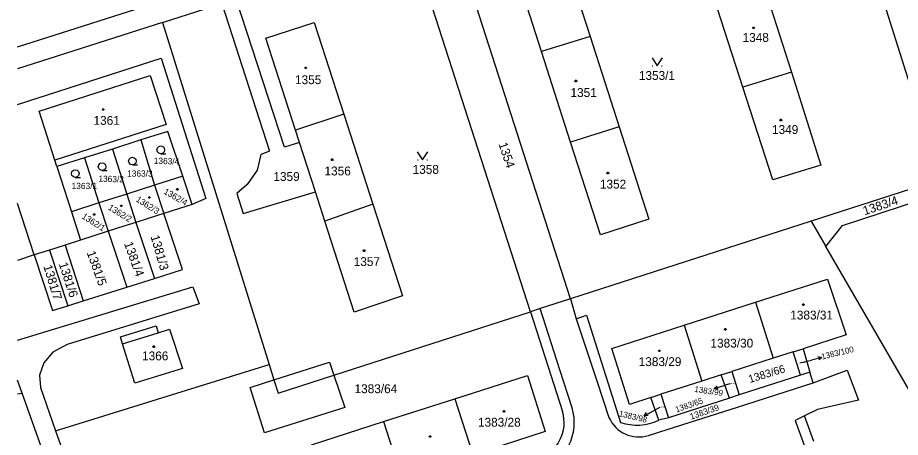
# Model space of a CAD drawing. Extents: x -621797 to -620972, y -1175539 to -1174697.
# Drawn here: x -621790.3 to -621620.7, y -1175421.5 to -1175341 of the extents above; entities that cross this region are included whole.
import ezdxf

# ---------------------------------------------------------------- set-up
doc = ezdxf.new("R2010")
doc.units = 0
for name, color, linetype in [('INZ mimo EON - nadz', 7, 'Continuous'), ('Rozvod plynu EON', 7, 'Continuous'), ('SDEL EON', 7, 'Continuous'), ('SDEL EON - popis', 7, 'Continuous'), ('Silnoproud EON', 7, 'Continuous'), ('Silnoproud EON - popis', 7, 'Continuous')]:
    doc.layers.add(name, color=color, linetype=linetype)

msp = doc.modelspace()

# ---------------------------------------------------------------- linework, layer by layer
at = {"layer": 'INZ mimo EON - nadz'}
for p, q in [((-621639.98, -1175407.25), (-621637.75, -1175406.68)), ((-621635.807, -1175406.166), (-621637.75, -1175406.68)), ((-621656.444, -1175412.173), (-621654.52, -1175411.59)), ((-621653.46, -1175411.26), (-621654.52, -1175411.59)), ((-621669.899, -1175417.383), (-621668.13, -1175416.43)), ((-621666.93, -1175415.8), (-621668.13, -1175416.43))]:
    msp.add_line(p, q, dxfattribs=at)
for points in [[(-621636.54, -1175406.013), (-621635.807, -1175406.166), (-621636.369, -1175406.661)], [(-621655.705, -1175412.299), (-621656.444, -1175412.173), (-621655.9, -1175411.658)], [(-621669.151, -1175417.361), (-621669.899, -1175417.383), (-621669.469, -1175416.771)]]:
    msp.add_lwpolyline(points, dxfattribs=at)
at = {"layer": 'Rozvod plynu EON'}
for points in [[(-621648.8, -1175342.77), (-621648.71, -1175342.92), (-621648.8, -1175343.07), (-621648.98, -1175343.07), (-621649.07, -1175342.92), (-621648.98, -1175342.77)], [(-621734.88, -1175350.45), (-621734.79, -1175350.6), (-621734.88, -1175350.75), (-621735.06, -1175350.75), (-621735.15, -1175350.6), (-621735.06, -1175350.45)], [(-621682.94, -1175352.95), (-621682.85, -1175353.1), (-621682.94, -1175353.25), (-621683.12, -1175353.25), (-621683.21, -1175353.1), (-621683.12, -1175352.95)], [(-621773.79, -1175358.44), (-621773.7, -1175358.59), (-621773.79, -1175358.74), (-621773.97, -1175358.74), (-621774.06, -1175358.59), (-621773.97, -1175358.44)], [(-621643.56, -1175360.44), (-621643.47, -1175360.59), (-621643.56, -1175360.74), (-621643.74, -1175360.74), (-621643.83, -1175360.59), (-621643.74, -1175360.44)], [(-621729.78, -1175368.05), (-621729.69, -1175368.2), (-621729.78, -1175368.35), (-621729.96, -1175368.35), (-621730.05, -1175368.2), (-621729.96, -1175368.05)], [(-621676.8, -1175370.62), (-621676.71, -1175370.77), (-621676.8, -1175370.92), (-621676.98, -1175370.92), (-621677.07, -1175370.77), (-621676.98, -1175370.62)], [(-621759.54, -1175373.78), (-621759.45, -1175373.93), (-621759.54, -1175374.08), (-621759.72, -1175374.08), (-621759.81, -1175373.93), (-621759.72, -1175373.78)], [(-621764.92, -1175375.33), (-621764.83, -1175375.48), (-621764.92, -1175375.63), (-621765.1, -1175375.63), (-621765.19, -1175375.48), (-621765.1, -1175375.33)], [(-621770.3, -1175376.94), (-621770.21, -1175377.09), (-621770.3, -1175377.24), (-621770.48, -1175377.24), (-621770.57, -1175377.09), (-621770.48, -1175376.94)], [(-621775.51, -1175378.6), (-621775.42, -1175378.75), (-621775.51, -1175378.9), (-621775.69, -1175378.9), (-621775.78, -1175378.75), (-621775.69, -1175378.6)], [(-621723.65, -1175385.54), (-621723.56, -1175385.69), (-621723.65, -1175385.84), (-621723.83, -1175385.84), (-621723.92, -1175385.69), (-621723.83, -1175385.54)], [(-621639.25, -1175395.92), (-621639.16, -1175396.07), (-621639.25, -1175396.22), (-621639.43, -1175396.22), (-621639.52, -1175396.07), (-621639.43, -1175395.92)], [(-621654.23, -1175400.65), (-621654.14, -1175400.8), (-621654.23, -1175400.95), (-621654.41, -1175400.95), (-621654.5, -1175400.8), (-621654.41, -1175400.65)], [(-621764.06, -1175403.95), (-621763.97, -1175404.1), (-621764.06, -1175404.25), (-621764.24, -1175404.25), (-621764.33, -1175404.1), (-621764.24, -1175403.95)], [(-621666.92, -1175404.77), (-621666.83, -1175404.92), (-621666.92, -1175405.07), (-621667.1, -1175405.07), (-621667.19, -1175404.92), (-621667.1, -1175404.77)], [(-621696.76, -1175416.36), (-621696.67, -1175416.51), (-621696.76, -1175416.66), (-621696.94, -1175416.66), (-621697.03, -1175416.51), (-621696.94, -1175416.36)], [(-621710.97, -1175421.21), (-621710.88, -1175421.36), (-621710.97, -1175421.51), (-621711.15, -1175421.51), (-621711.24, -1175421.36), (-621711.15, -1175421.21)]]:
    msp.add_lwpolyline(points, close=True, dxfattribs=at)
at = {"layer": 'SDEL EON'}
for p, q in [((-621668.36, -1175350.19), (-621668.26, -1175350.19)), ((-621666.56, -1175350.19), (-621666.46, -1175350.19)), ((-621713.46, -1175368.24), (-621713.36, -1175368.24)), ((-621711.66, -1175368.24), (-621711.56, -1175368.24))]:
    msp.add_line(p, q, dxfattribs=at)
for points in [[(-621668.41, -1175348.69), (-621667.41, -1175350.19), (-621666.41, -1175348.69)], [(-621762.79, -1175367.07), (-621763.17, -1175366.97), (-621763.44, -1175366.7), (-621763.54, -1175366.33), (-621763.44, -1175365.96), (-621763.17, -1175365.69), (-621762.8, -1175365.59), (-621762.43, -1175365.69), (-621762.16, -1175365.96), (-621762.06, -1175366.34), (-621762.16, -1175366.72), (-621762.43, -1175366.99), (-621762.81, -1175367.09), (-621761.81, -1175367.09)], [(-621768.25, -1175369.22), (-621768.63, -1175369.12), (-621768.9, -1175368.85), (-621769, -1175368.48), (-621768.9, -1175368.11), (-621768.63, -1175367.84), (-621768.26, -1175367.74), (-621767.89, -1175367.84), (-621767.62, -1175368.11), (-621767.52, -1175368.49), (-621767.62, -1175368.87), (-621767.89, -1175369.14), (-621768.27, -1175369.24), (-621767.27, -1175369.24)], [(-621713.51, -1175366.74), (-621712.51, -1175368.24), (-621711.51, -1175366.74)], [(-621774.09, -1175370.3), (-621774.47, -1175370.2), (-621774.74, -1175369.93), (-621774.84, -1175369.56), (-621774.74, -1175369.19), (-621774.47, -1175368.92), (-621774.1, -1175368.82), (-621773.73, -1175368.92), (-621773.46, -1175369.19), (-621773.36, -1175369.57), (-621773.46, -1175369.95), (-621773.73, -1175370.22), (-621774.11, -1175370.32), (-621773.11, -1175370.32)], [(-621779.22, -1175371.62), (-621779.6, -1175371.52), (-621779.87, -1175371.25), (-621779.97, -1175370.88), (-621779.87, -1175370.51), (-621779.6, -1175370.24), (-621779.23, -1175370.14), (-621778.86, -1175370.24), (-621778.59, -1175370.51), (-621778.49, -1175370.89), (-621778.59, -1175371.27), (-621778.86, -1175371.54), (-621779.24, -1175371.64), (-621778.24, -1175371.64)]]:
    msp.add_lwpolyline(points, dxfattribs=at)
at = {"layer": 'SDEL EON - popis'}
for p, q in [((-621790.31, -1175346.561), (-621755.77, -1175335.52)), ((-621786.19, -1175358.92), (-621764.84, -1175352.09)), ((-621764.84, -1175352.09), (-621761.79, -1175361.48)), ((-621783.14, -1175368.33), (-621786.19, -1175358.92)), ((-621761.79, -1175361.48), (-621783.14, -1175368.33)), ((-621782.75, -1175369.56), (-621783.14, -1175368.33)), ((-621770.15, -1175403.57), (-621763.29, -1175401.44)), ((-621741.05, -1175410.49), (-621730.39, -1175407.07)), ((-621730.39, -1175407.07), (-621729.54, -1175409.59)), ((-621745.62, -1175411.95), (-621741.05, -1175410.49)), ((-621729.54, -1175409.59), (-621727.46, -1175415.77)), ((-621742.86, -1175420.65), (-621745.62, -1175411.95)), ((-621727.46, -1175415.77), (-621742.86, -1175420.65))]:
    msp.add_line(p, q, dxfattribs=at)
at = {"layer": 'Silnoproud EON'}
for p, q in [((-621684.09, -1175394.94), (-621706.99, -1175323.82)), ((-621691.78, -1175397.42), (-621714.66, -1175326.34)), ((-621686.01, -1175326.76), (-621680.29, -1175344.56)), ((-621689.64, -1175347.47), (-621695.36, -1175329.7)), ((-621647.19, -1175333.9), (-621641.63, -1175351.45)), ((-621617.7, -1175357.4), (-621624.53, -1175335.83)), ((-621739.01, -1175365.79), (-621748.33, -1175337.34)), ((-621650.96, -1175354.32), (-621656.61, -1175336.8)), ((-621762.48, -1175341.91), (-621751.05, -1175338.26)), ((-621751.05, -1175338.26), (-621741.9, -1175366.61)), ((-621762.48, -1175341.91), (-621790.31, -1175350.792)), ((-621762.48, -1175341.91), (-621741.97, -1175407.54)), ((-621742.62, -1175344.91), (-621733.31, -1175341.91)), ((-621733.31, -1175341.91), (-621727.62, -1175359.51)), ((-621736.92, -1175362.55), (-621742.62, -1175344.91)), ((-621680.29, -1175344.56), (-621689.64, -1175347.47)), ((-621680.29, -1175344.56), (-621674.72, -1175361.89)), ((-621684.05, -1175364.85), (-621689.64, -1175347.47)), ((-621790.31, -1175357.631), (-621762.76, -1175348.73)), ((-621762.76, -1175348.73), (-621754.14, -1175375.67)), ((-621641.63, -1175351.45), (-621650.96, -1175354.32)), ((-621641.63, -1175351.45), (-621635.98, -1175369.27)), ((-621645.22, -1175372.11), (-621650.96, -1175354.32)), ((-621727.62, -1175359.51), (-621736.92, -1175362.55)), ((-621727.62, -1175359.51), (-621722.04, -1175376.78)), ((-621761.43, -1175362.8), (-621766.62, -1175364.44)), ((-621758.58, -1175371.37), (-621761.43, -1175362.8)), ((-621736.15, -1175364.91), (-621736.92, -1175362.55)), ((-621674.72, -1175361.89), (-621684.05, -1175364.85)), ((-621674.72, -1175361.89), (-621669.01, -1175379.63)), ((-621766.62, -1175364.44), (-621772.08, -1175366.18)), ((-621766.62, -1175364.44), (-621764.01, -1175373.1)), ((-621772.08, -1175366.18), (-621777.46, -1175367.88)), ((-621772.08, -1175366.18), (-621769.34, -1175374.81)), ((-621736.15, -1175364.91), (-621739.01, -1175365.79)), ((-621733.08, -1175374.42), (-621736.15, -1175364.91)), ((-621678.32, -1175382.66), (-621684.05, -1175364.85)), ((-621777.46, -1175367.88), (-621782.75, -1175369.56)), ((-621777.46, -1175367.88), (-621774.71, -1175376.52)), ((-621743.58, -1175367.24), (-621744.3, -1175370.23)), ((-621741.9, -1175366.61), (-621743.58, -1175367.24)), ((-621782.75, -1175369.56), (-621779.99, -1175378.21)), ((-621635.98, -1175369.27), (-621645.22, -1175372.11)), ((-621758.58, -1175371.37), (-621764.01, -1175373.1)), ((-621756.77, -1175376.83), (-621758.58, -1175371.37)), ((-621744.3, -1175370.23), (-621746.19, -1175373)), ((-621764.01, -1175373.1), (-621769.34, -1175374.81)), ((-621764.01, -1175373.1), (-621762.24, -1175378.57)), ((-621746.19, -1175373), (-621748.21, -1175374.71)), ((-621615.01, -1175372.67), (-621637.81, -1175380.02)), ((-621769.34, -1175374.81), (-621774.71, -1175376.52)), ((-621769.34, -1175374.81), (-621767.57, -1175380.27)), ((-621748.21, -1175374.71), (-621746.95, -1175378.56)), ((-621746.95, -1175378.56), (-621733.08, -1175374.42)), ((-621731.27, -1175380.03), (-621733.08, -1175374.42)), ((-621787.11, -1175386.5), (-621790.31, -1175376.66)), ((-621774.71, -1175376.52), (-621779.99, -1175378.21)), ((-621774.71, -1175376.52), (-621772.91, -1175381.97)), ((-621754.14, -1175375.67), (-621756.77, -1175376.83)), ((-621631.78, -1175380.83), (-621614.31, -1175375.13)), ((-621779.99, -1175378.21), (-621778.25, -1175383.67)), ((-621759.22, -1175377.61), (-621762.24, -1175378.57)), ((-621756.77, -1175376.83), (-621759.22, -1175377.61)), ((-621722.04, -1175376.78), (-621731.27, -1175380.03)), ((-621722.04, -1175376.78), (-621716.36, -1175394.34)), ((-621765.21, -1175379.52), (-621767.57, -1175380.27)), ((-621762.24, -1175378.57), (-621765.21, -1175379.52)), ((-621758.64, -1175389.32), (-621762.24, -1175378.57)), ((-621725.63, -1175397.48), (-621731.27, -1175380.03)), ((-621637.81, -1175380.02), (-621684.09, -1175394.94)), ((-621669.01, -1175379.63), (-621678.32, -1175382.66)), ((-621637.81, -1175380.02), (-621634.99, -1175384.89)), ((-621769.91, -1175381.01), (-621772.91, -1175381.97)), ((-621767.57, -1175380.27), (-621769.91, -1175381.01)), ((-621767.57, -1175380.27), (-621764, -1175391.01)), ((-621634.99, -1175384.89), (-621631.78, -1175380.83)), ((-621772.91, -1175381.97), (-621778.25, -1175383.67)), ((-621772.91, -1175381.97), (-621769.36, -1175392.7)), ((-621781.2, -1175384.61), (-621784.16, -1175385.56)), ((-621778.25, -1175383.67), (-621781.2, -1175384.61)), ((-621781.2, -1175384.61), (-621777.69, -1175395.32)), ((-621618.63, -1175413.08), (-621634.99, -1175384.89)), ((-621787.11, -1175386.5), (-621790.31, -1175387.589)), ((-621784.16, -1175385.56), (-621787.11, -1175386.5)), ((-621787.11, -1175386.5), (-621783.63, -1175397.19)), ((-621784.16, -1175385.56), (-621780.66, -1175396.26)), ((-621764, -1175391.01), (-621758.64, -1175389.32)), ((-621769.36, -1175392.7), (-621764, -1175391.01)), ((-621648.55, -1175395.6), (-621634.69, -1175391.13)), ((-621634.69, -1175391.13), (-621631.13, -1175401.86)), ((-621790.31, -1175402.898), (-621756.66, -1175392.66)), ((-621777.69, -1175395.32), (-621769.36, -1175392.7)), ((-621756.66, -1175392.66), (-621755.41, -1175395.92)), ((-621780.66, -1175396.26), (-621777.69, -1175395.32)), ((-621716.36, -1175394.34), (-621725.63, -1175397.48)), ((-621684.09, -1175394.94), (-621689.91, -1175396.82)), ((-621684.09, -1175394.94), (-621683, -1175398.75)), ((-621783.63, -1175397.19), (-621780.66, -1175396.26)), ((-621755.41, -1175395.92), (-621780.79, -1175403.73)), ((-621689.91, -1175396.82), (-621691.78, -1175397.42)), ((-621686.12, -1175408.54), (-621689.91, -1175396.82)), ((-621662.24, -1175400.02), (-621648.55, -1175395.6)), ((-621648.55, -1175395.6), (-621645.15, -1175406.35)), ((-621729.54, -1175409.59), (-621691.78, -1175397.42)), ((-621691.78, -1175397.42), (-621685.63, -1175416.55)), ((-621683, -1175398.75), (-621681.02, -1175398.04)), ((-621683, -1175398.75), (-621678.96, -1175410.87)), ((-621681.02, -1175398.04), (-621674.44, -1175418.66)), ((-621770.56, -1175402.25), (-621763.7, -1175400.11)), ((-621763.7, -1175400.11), (-621763.29, -1175401.44)), ((-621676.13, -1175404.49), (-621662.24, -1175400.02)), ((-621662.24, -1175400.02), (-621658.81, -1175410.71)), ((-621763.29, -1175401.44), (-621761.11, -1175400.76)), ((-621761.11, -1175400.76), (-621758.61, -1175408.33)), ((-621631.13, -1175401.86), (-621639.39, -1175404.51)), ((-621780.79, -1175403.73), (-621783.56, -1175405.2)), ((-621770.15, -1175403.57), (-621770.56, -1175402.25)), ((-621767.8, -1175411.14), (-621770.15, -1175403.57)), ((-621783.56, -1175405.2), (-621785.25, -1175407.2)), ((-621672.72, -1175415.19), (-621676.13, -1175404.49)), ((-621641.29, -1175405.12), (-621645.15, -1175406.35)), ((-621641.29, -1175405.12), (-621639.39, -1175404.51)), ((-621639.86, -1175409.59), (-621641.29, -1175405.12)), ((-621639.39, -1175404.51), (-621638.06, -1175409.01)), ((-621785.25, -1175407.2), (-621786.13, -1175409.56)), ((-621645.15, -1175406.35), (-621653.1, -1175408.9)), ((-621783.01, -1175420.3), (-621741.97, -1175407.54)), ((-621758.61, -1175408.33), (-621767.8, -1175411.14)), ((-621741.97, -1175407.54), (-621741.05, -1175410.49)), ((-621683.76, -1175415.85), (-621686.12, -1175408.54)), ((-621655.1, -1175409.54), (-621653.1, -1175408.9)), ((-621653.1, -1175408.9), (-621651.67, -1175413.38)), ((-621637.46, -1175411.03), (-621630.9, -1175408.6)), ((-621630.9, -1175408.6), (-621628.71, -1175414.36)), ((-621789.42, -1175413.07), (-621790.31, -1175410.55)), ((-621786.13, -1175409.56), (-621785.94, -1175411.98)), ((-621741.05, -1175410.49), (-621740.25, -1175413.04)), ((-621740.25, -1175413.04), (-621729.54, -1175409.59)), ((-621706.29, -1175414.11), (-621692.33, -1175409.65)), ((-621692.33, -1175409.65), (-621688.94, -1175420.43)), ((-621655.1, -1175409.54), (-621658.81, -1175410.71)), ((-621653.51, -1175413.98), (-621655.1, -1175409.54)), ((-621639.86, -1175409.59), (-621651.67, -1175413.38)), ((-621638.06, -1175409.01), (-621639.86, -1175409.59)), ((-621637.46, -1175411.03), (-621638.06, -1175409.01)), ((-621785.94, -1175411.98), (-621783.01, -1175420.3)), ((-621678.96, -1175410.87), (-621676.68, -1175417.7)), ((-621658.81, -1175410.71), (-621666.72, -1175413.26)), ((-621651.99, -1175415.72), (-621637.46, -1175411.03)), ((-621790.31, -1175413.199), (-621789.42, -1175413.07)), ((-621778.35, -1175444.38), (-621789.42, -1175413.07)), ((-621668.63, -1175413.87), (-621672.72, -1175415.19)), ((-621668.63, -1175413.87), (-621666.72, -1175413.26)), ((-621667.09, -1175418.24), (-621668.63, -1175413.87)), ((-621666.72, -1175413.26), (-621665.24, -1175417.75)), ((-621653.51, -1175413.98), (-621665.24, -1175417.75)), ((-621651.67, -1175413.38), (-621653.51, -1175413.98)), ((-621719.99, -1175418.49), (-621706.29, -1175414.11)), ((-621706.29, -1175414.11), (-621702.85, -1175424.84)), ((-621628.71, -1175414.36), (-621636.63, -1175416.21)), ((-621665.29, -1175419.96), (-621651.99, -1175415.72)), ((-621639.1, -1175417.4), (-621640.9, -1175418.27)), ((-621636.63, -1175416.21), (-621639.1, -1175417.4)), ((-621637.33, -1175422.33), (-621639.1, -1175417.4)), ((-621733.86, -1175422.93), (-621719.99, -1175418.49)), ((-621719.99, -1175418.49), (-621716.56, -1175429.27)), ((-621665.24, -1175417.75), (-621667.09, -1175418.24)), ((-621640.9, -1175418.27), (-621639.19, -1175423)), ((-621783.01, -1175420.3), (-621773.63, -1175446.97)), ((-621688.94, -1175420.43), (-621697.18, -1175423.07)), ((-621669.1, -1175421.17), (-621665.29, -1175419.96))]:
    msp.add_line(p, q, dxfattribs=at)
for centre, radius, start, end in [((-621692.397, -1175418.724), 7.108, 284.97803, 17.80993), ((-621693.2, -1175418.647), 9.846, 290.32658, 16.50522), ((-621670.947, -1175415.191), 6.258, 203.63791, 287.16703), ((-621671.29, -1175409.264), 9.91, 251.46619, 295.07479)]:
    msp.add_arc(centre, radius, start, end, dxfattribs=at)

# ---------------------------------------------------------------- texts
at = {"layer": 'INZ mimo EON - nadz'}
for s, rotation, p in [('1383/100', 13.5791, (-621635.724, -1175406.611)), ('1383/99', 351.39502, (-621660.318, -1175412.786)), ('1383/98', 346.52488, (-621674.858, -1175417.452))]:
    msp.add_text(s, height=1.14, rotation=rotation, dxfattribs=at).set_placement(p)
at = {"layer": 'Silnoproud EON - popis'}
for s, height, p in [('1348', 1.7, (-621651.007, -1175345.61)), ('1353/1', 1.7, (-621670.937, -1175352.91)), ('1355', 1.7, (-621737.017, -1175353.72)), ('1351', 1.7, (-621684.077, -1175356.19)), ('1361', 1.7, (-621775.737, -1175361.53)), ('1349', 1.7, (-621645.357, -1175363.28)), ('1356', 1.7, (-621731.347, -1175371.24)), ('1358', 1.7, (-621714.417, -1175370.94)), ('1363/3', 1.2, (-621769.273, -1175371.48)), ('1359', 1.7, (-621741.167, -1175372.3)), ('1363/1', 1.2, (-621779.943, -1175373.86)), ('1352', 1.7, (-621678.427, -1175373.76)), ('1357', 1.7, (-621725.737, -1175388.64)), ('1383/31', 1.7, (-621641.847, -1175398.9)), ('1383/30', 1.7, (-621657.177, -1175404.29)), ('1366', 1.7, (-621766.407, -1175406.74)), ('1383/29', 1.7, (-621670.977, -1175407.84)), ('1383/100', 0.2, (-621639.934, -1175407.25)), ('1383/64', 1.7, (-621725.577, -1175413.04)), ('1383/99', 0.2, (-621653.414, -1175411.26)), ('1383/98', 0.2, (-621666.884, -1175415.8)), ('1383/28', 1.7, (-621701.858, -1175419.47))]:
    msp.add_text(s, height=height, dxfattribs=at).set_placement(p)
for s, height, rotation, p in [('1354', 1.7, 288.88532, (-621697.943, -1175365.212)), ('1363/4', 1.2, 358.21321, (-621764.173, -1175369.019)), ('1363/2', 1.2, 358.21321, (-621774.813, -1175372.449)), ('1362/4', 1.2, 330.31017, (-621762.369, -1175374.677)), ('1362/3', 1.2, 327.61727, (-621767.706, -1175376.138)), ('1383/4', 1.7, 17.99087, (-621627.577, -1175378.899)), ('1362/2', 1.2, 328.4767, (-621773.034, -1175377.715)), ('1362/1', 1.2, 327.61727, (-621778.096, -1175379.398)), ('1381/3', 1.7, 286.19242, (-621764.79, -1175382.957)), ('1381/4', 1.7, 289.80205, (-621769.897, -1175384.309)), ('1381/5', 1.7, 289.80205, (-621777.067, -1175386.059)), ('1381/7', 1.7, 287.10915, (-621785.394, -1175388.685)), ('1381/6', 1.7, 288.02588, (-621782.428, -1175388.213)), ('1383/66', 1.5, 17.07414, (-621649.619, -1175411.108)), ('1383/65', 1.14, 19.19409, (-621663.701, -1175416.773)), ('1383/39', 1.2, 18.90761, (-621660.888, -1175418.15))]:
    msp.add_text(s, height=height, rotation=rotation, dxfattribs=at).set_placement(p)

doc.saveas('drawing.dxf')
